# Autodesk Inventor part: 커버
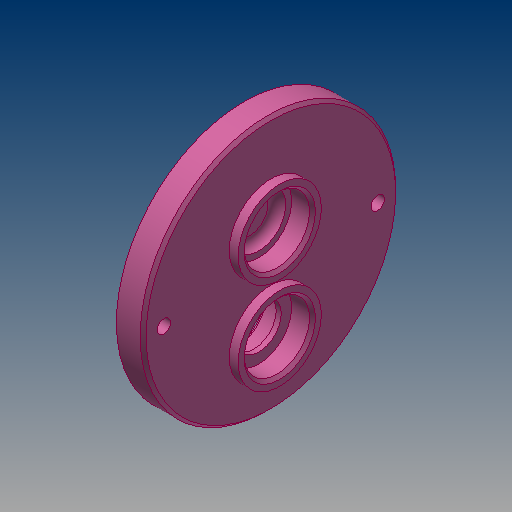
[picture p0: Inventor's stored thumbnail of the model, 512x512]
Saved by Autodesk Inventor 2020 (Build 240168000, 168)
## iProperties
Created: 2016-02
Part Number: 커버
Material: 알루미늄 6061
Document SubType Name: Modeling
Designer: mduedu
Density: 2.71 g/cm^3
Appearance: 분홍색
Author: mduedu
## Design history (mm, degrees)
sketch "스케치1"
  geometry: C1 r 43 at (0, 0); 1 further point
  constraints: 1 centre point, 1 coincident
  dimensions: "d0" = 86 diameter of C1
extrude "돌출1" new body sketch "스케치1" distance "d1" = 9; taper "d2" = 0 deg
sketch "스케치2"
  geometry: C1 r 14 at (0, 11); 1 further point
  constraints: 1 centre point, 1 vertical alignment
  dimensions: "d3" = 28 diameter of C1; "d6" = 11 distance of C1.centre point (0, 0)
extrude "돌출2" join sketch "스케치2" distance "d7" = 3; taper "d8" = 0 deg
sketch "스케치3"
  geometry: C1 r 14 at (0, -20); 1 further point
  constraints: 1 centre point, 1 vertical alignment
  dimensions: "d9" = 28 diameter of C1; "d10" = 20 distance of C1.centre point (0, 0)
extrude "돌출3" join sketch "스케치3" distance "d11" = 3; taper "d12" = 0 deg
hole "구멍1" diameter "d15" = 22; stored, may be unused: countersink angle "d19" = 90 deg, drill point angle "d21" = 0 deg; dims "d13" = 10, "d14" = 10, "d16" = 6, "d17" = 4, "d18" = 2, "d20" = 7
hole "구멍2" diameter "d24" = 18; stored, may be unused: countersink angle "d28" = 90 deg, drill point angle "d30" = 0 deg; dims "d25" = 6, "d26" = 4, "d27" = 2, "d29" = 3, "d95" = 10, "d96" = 10
fillet "모깎기7" dims "d97" = 3
hole "구멍3" diameter "d33" = 22; stored, may be unused: countersink angle "d37" = 90 deg, drill point angle "d39" = 0 deg; dims "d34" = 6, "d35" = 4, "d36" = 2, "d38" = 7, "d73" = 10, "d74" = 10
sketch "스케치4"
  geometry: C1 r 14 at (0, -20) reference; C2 r 18 at (0, -20); 1 further point
  constraints: 1 centre point, 1 coincident
  dimensions: "d40" = 36 diameter of C2
extrude "돌출4" join sketch "스케치4" distance "d41" = 4; taper "d42" = 0 deg
hole "구멍4" diameter "d45" = 22; stored, may be unused: countersink angle "d49" = 90 deg, drill point angle "d51" = 0 deg; dims "d46" = 6, "d47" = 4, "d48" = 2, "d50" = 7.3, "d98" = 10, "d99" = 10
hole "구멍5" diameter "d54" = 15; stored, may be unused: countersink angle "d58" = 90 deg, drill point angle "d60" = 0 deg; dims "d52" = 10, "d53" = 10, "d55" = 6, "d56" = 4, "d57" = 2, "d59" = 7
chamfer "모따기1" distance "d63" = 1; stored, may be unused: second distance "d64" = 2, angle "d65" = 45 deg
chamfer "모따기3" distance "d100" = 0.7; stored, may be unused: second distance "d101" = 2, angle "d102" = 30 deg
sketch "스케치5" dims "d67" = 72
  geometry: 4 further points
  constraints: 2 horizontal alignment, 1 coincident, 5 other
  dimensions: "d71" = 360 deg dimension on point (0, 0) point (-36, 0) (derived)
sketch "스케치6"
  geometry: 2 further points
hole "구멍6" sketch "스케치6" at (-36, 0), (36, 0) diameter "d76" = 4.5; stored, may be unused: countersink angle "d80" = 90 deg, drill point angle "d82" = 0 deg; dims "d77" = 6, "d78" = 8, "d79" = 4.6, "d81" = 8
chamfer "모따기2" distance "d90" = 1; stored, may be unused: second distance "d91" = 2, angle "d92" = 45 deg
node "솔리드1"
